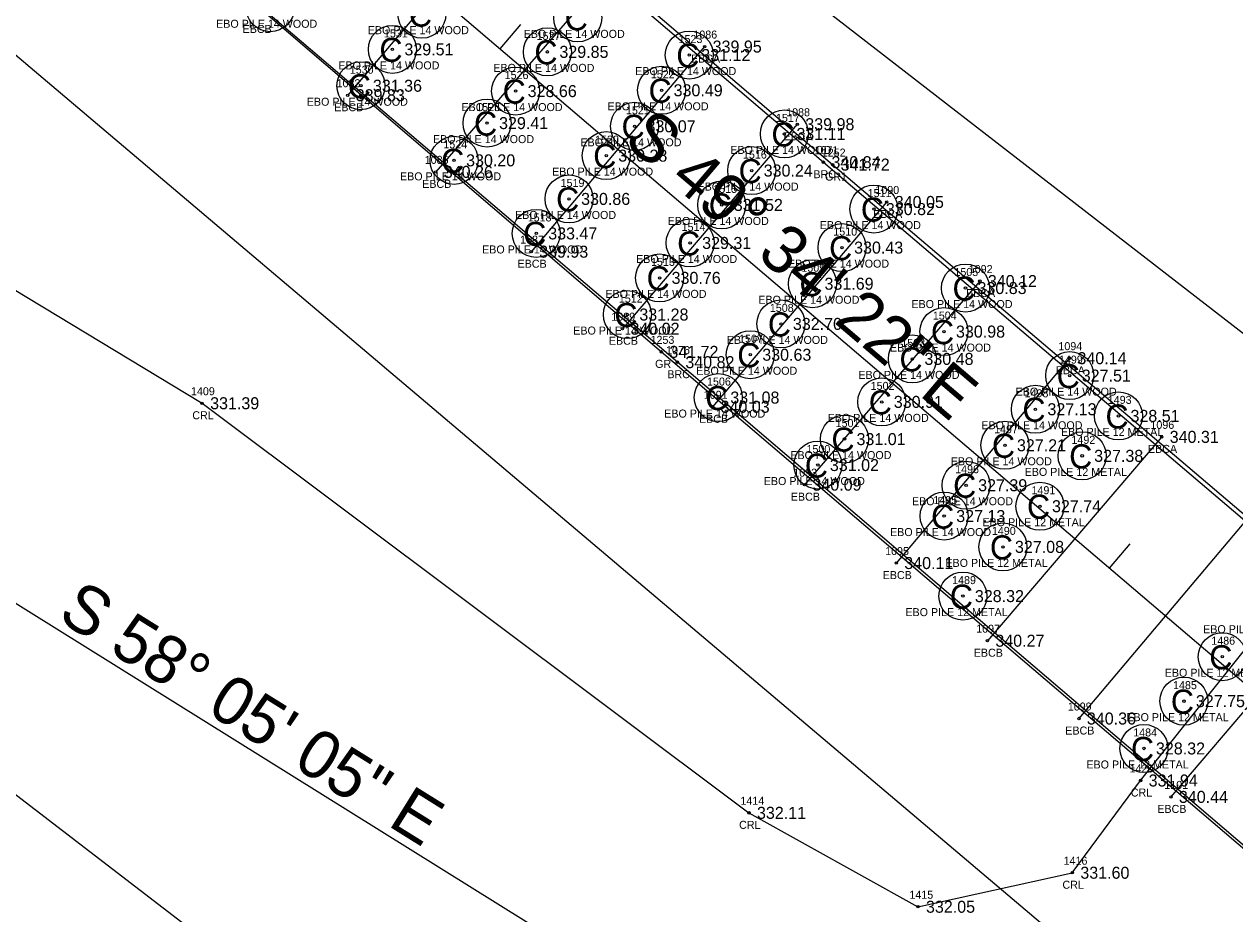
# Model space of a CAD drawing. Extents: x 2006517 to 2008868, y 1001613 to 1004633.
# Drawn here: x 2007680.3 to 2007831.6, y 1002930.6 to 1003041.7 of the extents above; entities that cross this region are included whole.
import ezdxf

# ---------------------------------------------------------------- set-up
doc = ezdxf.new("R2010")
doc.units = 0
for name, color, linetype in [('RD_EX_Bridge', 7, 'Continuous'), ('RD_EX_Bridge_txCode', 7, 'Continuous'), ('RD_EX_GuardRail', 7, 'Continuous'), ('RD_EX_GuardRail_txCode', 7, 'Continuous'), ('RD_EX_H2O', 7, 'Continuous'), ('RD_EX_H2O_txCode', 7, 'Continuous'), ('RD_EX_TX_Bridge_ELEV', 7, 'Continuous'), ('RD_EX_TX_GuardRail_ELEV', 7, 'Continuous'), ('RD_EX_TX_H2O_ELEV', 7, 'Continuous'), ('RD_EX_VEG', 7, 'Continuous'), ('RD_HC_Cl', 7, 'Continuous'), ('RD_HC_Data', 7, 'Continuous'), ('RD_HC_Data_Tic', 7, 'Continuous'), ('RD_SMD_Locator', 7, 'Continuous')]:
    doc.layers.add(name, color=color, linetype=linetype)

msp = doc.modelspace()

# ---------------------------------------------------------------- linework, layer by layer
at = {"layer": 'RD_EX_Bridge'}
for p, q in [((2007742.52, 1003058.51), (2007720.73, 1003032.86)), ((2007753.82, 1003048.7), (2007731.73, 1003023.29)), ((2007765.33, 1003038.94), (2007743.65, 1003013.32)), ((2007776.91, 1003029.24), (2007755.06, 1003003.7)), ((2007788.09, 1003019.53), (2007766.32, 1002993.95)), ((2007799.72, 1003009.65), (2007777.8, 1002984.22)), ((2007810.92, 1003000.02), (2007789.28, 1002974.43)), ((2007822.45, 1002990.19), (2007800.66, 1002964.73)), ((2007833.65, 1002980.54), (2007812.1, 1002955.01)), ((2007845.34, 1002970.76), (2007823.6, 1002945.22))]:
    msp.add_line(p, q, dxfattribs=at)
msp.add_lwpolyline([(2007687.31, 1003063.05), (2007707.28, 1003086.65), (2007780.18, 1003024.5), (2007853.73, 1002962.01), (2007935.92, 1002891.93), (2007915.63, 1002868.5), (2007835.4, 1002936.88), (2007761.92, 1002999.52), (2007687.36, 1003063.04)], dxfattribs=at)
for centre in [(2007711.04, 1003043.79), (2007729.99, 1003042.99), (2007749.47, 1003042.53), (2007726.31, 1003038.59), (2007745.68, 1003038.28), (2007763.41, 1003037.88), (2007722.37, 1003034.05), (2007741.71, 1003033.38), (2007759.95, 1003033.48), (2007738.14, 1003029.38), (2007756.57, 1003028.98), (2007775.3, 1003028.03), (2007734.02, 1003024.73), (2007753.03, 1003025.32), (2007771.21, 1003023.45), (2007748.39, 1003019.91), (2007767.47, 1003019.16), (2007786.48, 1003018.64), (2007744.28, 1003015.6), (2007763.52, 1003014.41), (2007782.51, 1003013.83), (2007759.7, 1003010.05), (2007778.81, 1003009.32), (2007797.93, 1003008.78), (2007755.67, 1003005.47), (2007774.86, 1003004.3), (2007795.24, 1003003.34), (2007771.03, 1003000.45), (2007791.3, 1002999.93), (2007810.96, 1002997.84), (2007767.04, 1002995.1), (2007787.47, 1002994.56), (2007806.67, 1002993.64), (2007817.05, 1002992.81), (2007782.81, 1002989.91), (2007802.86, 1002989.14), (2007812.51, 1002987.82), (2007779.48, 1002986.67), (2007798.01, 1002984.15), (2007795.26, 1002980.3), (2007807.24, 1002981.53), (2007802.61, 1002976.45), (2007797.6, 1002970.3), (2007830.02, 1002962.73), (2007825.22, 1002957.18), (2007820.23, 1002951.27)]:
    msp.add_circle(centre, 3, dxfattribs=at)
at = {"layer": 'RD_EX_GuardRail'}
for points in [[(2007643.64, 1003141.95), (2007706.71, 1003087.87), (2007781.32, 1003024.2), (2007854.58, 1002961.97), (2007936.8, 1002891.67), (2008015.14, 1002821.85)], [(2007623.33, 1003114.9), (2007686.46, 1003063.73), (2007759.92, 1003000.81), (2007833.42, 1002938.17), (2007916.12, 1002867.57), (2007997.28, 1002798.14)]]:
    msp.add_lwpolyline(points, dxfattribs=at)
at = {"layer": 'RD_EX_H2O'}
for points in [[(2007566.26, 1003088.08), (2007592.77, 1003066.93), (2007644.53, 1003029.41), (2007702.53, 1002994.39), (2007770.87, 1002943.23), (2007791.99, 1002931.5), (2007811.28, 1002935.75), (2007819.82, 1002947.27), (2007841.83, 1002974.87), (2007878.69, 1003000.86), (2007896.13, 1003066.77), (2007932.98, 1003128.11), (2007999.19, 1003157.72), (2008050.1, 1003143.6), (2008100.83, 1003134.29), (2008155.79, 1003098.62), (2008198.7, 1003074.43), (2008262, 1003078.26), (2008305.31, 1003092.03)], [(2007669.06, 1002953.29), (2007739.37, 1002899.33), (2007777.17, 1002873.15), (2007843, 1002887.34), (2007865.59, 1002908.46), (2007889.4, 1002933.96), (2007902.62, 1002951.59), (2007899.23, 1002956.7), (2007961.45, 1003046.31), (2007979.35, 1003079.78), (2008004.37, 1003099.33), (2008040.91, 1003092.79), (2008074.17, 1003079.43), (2008125.54, 1003053.8), (2008176.9, 1003027.12), (2008276.14, 1003020.76), (2008327.51, 1003029.06)]]:
    msp.add_lwpolyline(points, dxfattribs=at)
at = {"layer": 'RD_EX_VEG'}
for points in [[(2007395.89, 1003327.12), (2007429.8, 1003285.17), (2007467.04, 1003247.92), (2007498.61, 1003210.85), (2007670.4, 1003045.37), (2007967.56, 1002793.96), (2008054.61, 1002736.66), (2008078.76, 1002693.39), (2008113.28, 1002661.09), (2008135.36, 1002619.06), (2008159.5, 1002583.06), (2008222.5, 1002503.36), (2008272.84, 1002426.91), (2008323.43, 1002347.7), (2008431.42, 1002192), (2008479.95, 1002108.23), (2008533.09, 1002033.28), (2008631.97, 1001873.89), (2008775.08, 1001653.06)], [(2007473.93, 1003322.69), (2007503.07, 1003282.99), (2007540.25, 1003252.05), (2007579.27, 1003219.13), (2007642.18, 1003150.48), (2007952.5, 1002910.4), (2008017.59, 1002836.73), (2008047.98, 1002799.05), (2008087.42, 1002767.09), (2008121.48, 1002729.06), (2008151.49, 1002690.42), (2008185.86, 1002650.76), (2008208.76, 1002609.15), (2008254.04, 1002533.01), (2008311.38, 1002450.28), (2008360.35, 1002372.97), (2008409.06, 1002292.02), (2008460.63, 1002215.28), (2008512.48, 1002133.62), (2008564.88, 1002053.16), (2008614.62, 1001980.71), (2008661.43, 1001938.2)]]:
    msp.add_lwpolyline(points, dxfattribs=at)
at = {"layer": 'RD_HC_Cl'}
for p, q in [((2007559.77, 1003192.01), (2007994.36, 1002821.78)), ((2007624.66, 1003003.39), (2007793.45, 1002898.27))]:
    msp.add_line(p, q, dxfattribs=at)
at = {"layer": 'RD_HC_Data_Tic'}
for p, q in [((2007739.78, 1003038.66), (2007742.38, 1003041.7)), ((2007815.91, 1002973.81), (2007818.5, 1002976.85))]:
    msp.add_line(p, q, dxfattribs=at)
at = {"layer": 'RD_SMD_Locator'}
for centre in [(2007726.31, 1003038.59), (2007745.68, 1003038.28), (2007763.41, 1003037.88), (2007765.33, 1003038.94), (2007722.37, 1003034.05), (2007741.71, 1003033.38), (2007759.95, 1003033.48), (2007720.73, 1003032.86), (2007738.14, 1003029.38), (2007756.57, 1003028.98), (2007776.91, 1003029.24), (2007775.3, 1003028.03), (2007734.02, 1003024.73), (2007753.03, 1003025.32), (2007780.18, 1003024.5), (2007781.32, 1003024.2), (2007731.73, 1003023.29), (2007771.21, 1003023.45), (2007748.39, 1003019.91), (2007788.09, 1003019.53), (2007767.47, 1003019.16), (2007786.48, 1003018.64), (2007744.28, 1003015.6), (2007743.65, 1003013.32), (2007763.52, 1003014.41), (2007782.51, 1003013.83), (2007759.7, 1003010.05), (2007778.81, 1003009.32), (2007797.93, 1003008.78), (2007799.72, 1003009.65), (2007755.67, 1003005.47), (2007774.86, 1003004.3), (2007755.06, 1003003.7), (2007795.24, 1003003.34), (2007759.92, 1003000.81), (2007771.03, 1003000.45), (2007791.3, 1002999.93), (2007810.92, 1003000.02), (2007761.92, 1002999.52), (2007810.96, 1002997.84), (2007767.04, 1002995.1), (2007702.53, 1002994.39), (2007766.32, 1002993.95), (2007787.47, 1002994.56), (2007806.67, 1002993.64), (2007817.05, 1002992.81), (2007782.81, 1002989.91), (2007802.86, 1002989.14), (2007822.45, 1002990.19), (2007812.51, 1002987.82), (2007779.48, 1002986.67), (2007777.8, 1002984.22), (2007798.01, 1002984.15), (2007807.24, 1002981.53), (2007795.26, 1002980.3), (2007802.61, 1002976.45), (2007789.28, 1002974.43), (2007797.6, 1002970.3), (2007800.66, 1002964.73), (2007830.02, 1002962.73), (2007825.22, 1002957.18), (2007812.1, 1002955.01), (2007820.23, 1002951.27), (2007819.82, 1002947.27), (2007823.6, 1002945.22), (2007770.87, 1002943.23), (2007811.28, 1002935.75), (2007791.99, 1002931.5)]:
    msp.add_circle(centre, 0.15, dxfattribs=at)

# ---------------------------------------------------------------- texts
at = {"layer": 'RD_EX_Bridge'}
for p in [(2007728.36, 1003041.43), (2007747.84, 1003040.97), (2007724.68, 1003037.03), (2007744.05, 1003036.72), (2007761.78, 1003036.32), (2007720.74, 1003032.49), (2007740.08, 1003031.82), (2007758.32, 1003031.92), (2007736.51, 1003027.82), (2007754.94, 1003027.42), (2007773.67, 1003026.46), (2007732.39, 1003023.17), (2007751.4, 1003023.76), (2007769.57, 1003021.89), (2007746.76, 1003018.35), (2007765.84, 1003017.6), (2007784.85, 1003017.08), (2007742.65, 1003014.04), (2007761.89, 1003012.85), (2007780.88, 1003012.26), (2007758.07, 1003008.49), (2007777.18, 1003007.76), (2007796.3, 1003007.22), (2007754.04, 1003003.91), (2007773.23, 1003002.74), (2007793.61, 1003001.77), (2007769.4, 1002998.89), (2007789.67, 1002998.37), (2007809.32, 1002996.28), (2007765.41, 1002993.54), (2007785.84, 1002993), (2007805.04, 1002992.08), (2007815.42, 1002991.24), (2007781.17, 1002988.35), (2007801.23, 1002987.58), (2007810.88, 1002986.26), (2007777.85, 1002985.1), (2007796.38, 1002982.59), (2007793.63, 1002978.73), (2007805.61, 1002979.97), (2007800.98, 1002974.89), (2007795.97, 1002968.74), (2007828.39, 1002961.17), (2007823.59, 1002955.62), (2007818.6, 1002949.71)]:
    msp.add_text('C', height=3, dxfattribs=at).set_placement(p)
at = {"layer": 'RD_EX_Bridge_txCode'}
for s, p in [('EBO PILE 14 WOOD', (2007704.28, 1003041.29)), ('EBCB', (2007707.59, 1003040.64)), ('EBO PILE 14 WOOD', (2007723.23, 1003040.49)), ('1531', (2007725.25, 1003040.09)), ('EBO PILE 14 WOOD', (2007742.71, 1003040.03)), ('1527', (2007744.33, 1003039.78)), ('1086', (2007763.92, 1003039.94)), ('1523', (2007762.07, 1003039.38)), ('EBCA', (2007763.62, 1003036.94)), ('EBO PILE 14 WOOD', (2007719.55, 1003036.09)), ('1530', (2007720.98, 1003035.55)), ('EBO PILE 14 WOOD', (2007738.92, 1003035.78)), ('EBO PILE 14 WOOD', (2007756.65, 1003035.38)), ('1083', (2007719.34, 1003033.86)), ('1526', (2007740.34, 1003034.88)), ('1522', (2007758.61, 1003034.98)), ('EBO PILE 14 WOOD', (2007715.61, 1003031.55)), ('EBCB', (2007719.03, 1003030.86)), ('EBO PILE 14 WOOD', (2007734.94, 1003030.88)), ('1525', (2007736.79, 1003030.88)), ('EBO PILE 14 WOOD', (2007753.19, 1003030.98)), ('1521', (2007755.5, 1003030.48)), ('1517', (2007774.24, 1003029.53)), ('1088', (2007775.52, 1003030.24)), ('EBO PILE 14 WOOD', (2007731.38, 1003026.88)), ('1524', (2007732.68, 1003026.23)), ('EBO PILE 14 WOOD', (2007749.8, 1003026.48)), ('1520', (2007751.64, 1003026.82)), ('EBCA', (2007775.19, 1003027.24)), ('EBO PILE 14 WOOD', (2007768.54, 1003025.53)), ('1516', (2007770.12, 1003024.95)), ('1071', (2007779.07, 1003025.5)), ('1085', (2007730.35, 1003024.29)), ('EBO PILE 14 WOOD', (2007727.26, 1003022.23)), ('EBO PILE 14 WOOD', (2007746.26, 1003022.82)), ('BRC', (2007778.92, 1003022.5)), ('EBCB', (2007730.03, 1003021.29)), ('1519', (2007747.33, 1003021.41)), ('EBO PILE 14 WOOD', (2007764.44, 1003020.95)), ('1515', (2007766.41, 1003020.66)), ('1511', (2007785.7, 1003020.14)), ('1090', (2007786.67, 1003020.53)), ('EBO PILE 14 WOOD', (2007741.63, 1003017.41)), ('1518', (2007743.22, 1003017.1)), ('EBCA', (2007786.38, 1003017.53)), ('EBO PILE 14 WOOD', (2007760.71, 1003016.66)), ('1514', (2007762.46, 1003015.91)), ('EBO PILE 14 WOOD', (2007779.72, 1003016.14)), ('1087', (2007742.27, 1003014.32)), ('1510', (2007781.41, 1003015.33)), ('EBO PILE 14 WOOD', (2007737.52, 1003013.1)), ('EBCB', (2007741.95, 1003011.32)), ('EBO PILE 14 WOOD', (2007756.76, 1003011.91)), ('1513', (2007758.63, 1003011.55)), ('EBO PILE 14 WOOD', (2007775.75, 1003011.33)), ('1509', (2007777.42, 1003010.82)), ('1505', (2007796.55, 1003010.28)), ('1092', (2007798.34, 1003010.65)), ('EBO PILE 14 WOOD', (2007752.93, 1003007.55)), ('1512', (2007754.61, 1003006.97)), ('EBO PILE 14 WOOD', (2007772.04, 1003006.82)), ('EBCA', (2007798, 1003007.65)), ('1508', (2007773.48, 1003005.8)), ('EBO PILE 14 WOOD', (2007791.17, 1003006.28)), ('1504', (2007793.85, 1003004.84)), ('1089', (2007753.67, 1003004.7)), ('EBO PILE 14 WOOD', (2007748.91, 1003002.97)), ('EBO PILE 14 WOOD', (2007768.1, 1003001.8)), ('1507', (2007769.64, 1003001.95)), ('EBCB', (2007753.36, 1003001.7)), ('1076', (2007760.51, 1003000.52)), ('EBO PILE 14 WOOD', (2007788.48, 1003000.84)), ('1503', (2007789.91, 1003001.43)), ('1094', (2007809.54, 1003001.02)), ('1499', (2007809.61, 1002999.34)), ('BRC', (2007760.67, 1002997.52)), ('EBO PILE 14 WOOD', (2007764.27, 1002997.95)), ('EBO PILE 14 WOOD', (2007784.54, 1002997.43)), ('EBCA', (2007809.21, 1002998.02)), ('1506', (2007765.63, 1002996.6)), ('1502', (2007786.08, 1002996.06)), ('1091', (2007765.22, 1002994.95)), ('EBO PILE 14 WOOD', (2007804.19, 1002995.34)), ('1498', (2007805.32, 1002995.14)), ('1493', (2007815.71, 1002994.31)), ('EBO PILE 14 WOOD', (2007760.28, 1002992.6)), ('EBCB', (2007764.62, 1002991.95)), ('EBO PILE 14 WOOD', (2007780.7, 1002992.06)), ('1501', (2007781.7, 1002991.41)), ('1096', (2007821.04, 1002991.19)), ('EBO PILE 14 WOOD', (2007799.91, 1002991.14)), ('1497', (2007801.51, 1002990.64)), ('EBO PILE 12 METAL', (2007809.86, 1002990.31)), ('1500', (2007778.06, 1002988.17)), ('1492', (2007811.17, 1002989.32)), ('EBCA', (2007820.73, 1002988.19)), ('EBO PILE 14 WOOD', (2007776.04, 1002987.41)), ('EBO PILE 14 WOOD', (2007796.09, 1002986.64)), ('1093', (2007776.41, 1002985.22)), ('1496', (2007796.64, 1002985.65)), ('EBO PILE 12 METAL', (2007805.32, 1002985.32)), ('EBO PILE 14 WOOD', (2007772.72, 1002984.17)), ('EBCB', (2007776.1, 1002982.22)), ('1491', (2007806.18, 1002983.03)), ('EBO PILE 14 WOOD', (2007791.24, 1002981.65)), ('1495', (2007793.92, 1002981.8)), ('EBO PILE 14 WOOD', (2007788.5, 1002977.8)), ('EBO PILE 12 METAL', (2007800.05, 1002979.03)), ('1490', (2007801.23, 1002977.95)), ('1095', (2007787.89, 1002975.43)), ('EBO PILE 12 METAL', (2007795.42, 1002973.95)), ('EBCB', (2007787.58, 1002972.43)), ('1489', (2007796.26, 1002971.8)), ('EBO PILE 12 METAL', (2007790.42, 1002967.8)), ('1097', (2007799.27, 1002965.73)), ('EBO PILE 12 METAL', (2007827.63, 1002965.67)), ('1486', (2007828.65, 1002964.23)), ('EBCB', (2007798.96, 1002962.73)), ('EBO PILE 12 METAL', (2007822.83, 1002960.23)), ('1485', (2007823.87, 1002958.68)), ('1099', (2007810.72, 1002956.01)), ('EBO PILE 12 METAL', (2007818.03, 1002954.68)), ('EBCB', (2007810.4, 1002953.01)), ('1484', (2007818.89, 1002952.77)), ('EBO PILE 12 METAL', (2007813.04, 1002948.77)), ('1101', (2007822.78, 1002946.22)), ('EBCB', (2007821.9, 1002943.22))]:
    msp.add_text(s, height=1, dxfattribs=at).set_placement(p)
at = {"layer": 'RD_EX_GuardRail_txCode'}
for s, p in [('1252', (2007779.97, 1003025.2)), ('GR1', (2007780.37, 1003022.2)), ('1253', (2007758.57, 1003001.81)), ('GR', (2007759.14, 1002998.81))]:
    msp.add_text(s, height=1, dxfattribs=at).set_placement(p)
at = {"layer": 'RD_EX_H2O_txCode'}
for s, p in [('1409', (2007701.14, 1002995.39)), ('CRL', (2007701.3, 1002992.39)), ('1420', (2007818.43, 1002948.27)), ('CRL', (2007818.59, 1002945.27)), ('1414', (2007769.8, 1002944.23)), ('CRL', (2007769.64, 1002941.23)), ('1416', (2007810.19, 1002936.75)), ('CRL', (2007810.05, 1002933.75)), ('1415', (2007790.92, 1002932.5))]:
    msp.add_text(s, height=1, dxfattribs=at).set_placement(p)
at = {"layer": 'RD_EX_TX_Bridge_ELEV'}
for s, p in [('329.51', (2007727.81, 1003037.84)), ('339.95', (2007766.33, 1003038.19)), ('329.85', (2007747.18, 1003037.53)), ('331.12', (2007764.91, 1003037.13)), ('331.36', (2007723.87, 1003033.3)), ('339.83', (2007721.73, 1003032.11)), ('328.66', (2007743.21, 1003032.63)), ('330.49', (2007761.45, 1003032.73)), ('329.41', (2007739.64, 1003028.63)), ('330.07', (2007758.07, 1003028.23)), ('331.11', (2007776.8, 1003027.28)), ('339.98', (2007777.91, 1003028.49)), ('330.20', (2007735.52, 1003023.98)), ('330.28', (2007754.53, 1003024.57)), ('340.26', (2007732.73, 1003022.54)), ('330.24', (2007772.71, 1003022.7)), ('340.84', (2007781.18, 1003023.75)), ('330.86', (2007749.89, 1003019.16)), ('331.52', (2007768.97, 1003018.41)), ('340.05', (2007789.09, 1003018.78)), ('330.82', (2007787.98, 1003017.89)), ('333.47', (2007745.78, 1003014.85)), ('329.31', (2007765.02, 1003013.66)), ('339.93', (2007744.65, 1003012.57)), ('330.43', (2007784.01, 1003013.08)), ('330.76', (2007761.2, 1003009.3)), ('340.12', (2007800.72, 1003008.9)), ('331.69', (2007780.31, 1003008.57)), ('330.83', (2007799.43, 1003008.03)), ('331.28', (2007757.17, 1003004.72)), ('340.02', (2007756.06, 1003002.95)), ('332.70', (2007776.36, 1003003.55)), ('330.98', (2007796.74, 1003002.59)), ('340.82', (2007762.92, 1002998.77)), ('330.63', (2007772.53, 1002999.7)), ('330.48', (2007792.8, 1002999.18)), ('340.14', (2007811.92, 1002999.27)), ('327.51', (2007812.46, 1002997.09)), ('331.08', (2007768.54, 1002994.35)), ('330.91', (2007788.97, 1002993.81)), ('340.03', (2007767.32, 1002993.2)), ('327.13', (2007808.17, 1002992.89)), ('328.51', (2007818.55, 1002992.06)), ('340.31', (2007823.45, 1002989.44)), ('331.01', (2007784.31, 1002989.16)), ('327.21', (2007804.36, 1002988.39)), ('327.38', (2007814.01, 1002987.07)), ('331.02', (2007780.98, 1002985.92)), ('340.09', (2007778.8, 1002983.47)), ('327.39', (2007799.51, 1002983.4)), ('327.74', (2007808.74, 1002980.78)), ('327.13', (2007796.77, 1002979.55)), ('327.08', (2007804.11, 1002975.7)), ('340.11', (2007790.28, 1002973.68)), ('328.32', (2007799.1, 1002969.55)), ('340.27', (2007801.66, 1002963.98)), ('327.75', (2007826.72, 1002956.43)), ('340.36', (2007813.1, 1002954.26)), ('328.32', (2007821.73, 1002950.52)), ('340.44', (2007824.6, 1002944.47))]:
    msp.add_text(s, height=1.5, dxfattribs=at).set_placement(p)
at = {"layer": 'RD_EX_TX_GuardRail_ELEV'}
for p in [(2007782.32, 1003023.45), (2007760.92, 1003000.06)]:
    msp.add_text('341.72', height=1.5, dxfattribs=at).set_placement(p)
at = {"layer": 'RD_EX_TX_H2O_ELEV'}
for s, p in [('331.39', (2007703.53, 1002993.64)), ('331.94', (2007820.82, 1002946.52)), ('332.11', (2007771.87, 1002942.48)), ('331.60', (2007812.28, 1002935)), ('332.05', (2007792.99, 1002930.75))]:
    msp.add_text(s, height=1.5, dxfattribs=at).set_placement(p)
at = {"layer": 'RD_HC_Data'}
for s, rotation, p in [('S 49%%d 34\' 22" E', 319.5727, (2007755, 1003027.01)), ('S 58%%d 05\' 05" E', 328.0846, (2007684.3, 1002967.43))]:
    msp.add_text(s, height=6, rotation=rotation, dxfattribs=at).set_placement(p)

doc.saveas('drawing.dxf')
